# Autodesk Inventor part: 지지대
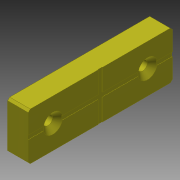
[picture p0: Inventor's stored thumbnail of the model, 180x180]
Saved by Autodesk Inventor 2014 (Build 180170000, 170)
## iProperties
Created: 2017-04
Part Number: 지지대
Material: 강철
Document SubType Name: Modeling
Designer: mduedu
Density: 7.85 g/cm^3
Mass: 97.8486 g
Surface Area: 48.4895 cm^2
Volume: 12.4648 cm^3
Appearance: 밝은 황색
Author: mduedu
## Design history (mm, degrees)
sketch "스케치1"
  geometry: L1 (23, -35)-(23, 35); L2 (0, -35)-(0, 35); L3 (0, 35)-(23, 35); L4 (0, -35)-(23, -35); 2 further points
  constraints: 8 end point, 2 parallel, 1 coincident, 1 midpoint, 1 perpendicular, 1 vertical
  dimensions: "d1" = 23 distance between parallel lines of L2 L1; "d15" = 70 distance of L1.start L1.end
extrude "돌출1" new body sketch "스케치1" distance "d2" = 8; taper "d3" = 0 deg
chamfer "모따기2" distance "d16" = 1; stored, may be unused: second distance "d17" = 2, angle "d18" = 45 deg
sketch "스케치2"
  geometry: L1 (1, -35)-(22, -35) reference; L2 (23, -34)-(23, 34) reference; L3 (22, 35)-(1, 35) reference; L4 (0, 34)-(0, -34) reference; L5 (11.5, 35)-(11.5, -35); L6 (23, 0)-(0, 0); L7 (1, -35)-(0, -34) reference; L8 (23, -34)-(22, -35) reference; L9 (22, 35)-(23, 34) reference; L10 (0, 34)-(1, 35) reference; 2 further points
  constraints: 4 end point, 4 midpoint, 1 point on line, 1 symmetric about line
  dimensions: "d7" = 12 distance from line of point (11.5, 23) L3
  node "투영된 루프1"
sketch "스케치3"
  geometry: 4 further points
  constraints: 2 coincident
hole "구멍1" sketch "스케치3" at (11.5, 23), (11.5, -23) diameter "d8" = 4.5; stored, may be unused: countersink angle "d12" = 90 deg, drill point angle "d14" = 0 deg; dims "d9" = 6, "d10" = 9.4, "d11" = 2, "d13" = 8
sketch "스케치4"
  geometry: L1 (-35, 22)-(-35, 1) reference; L2 (35, 1)-(35, 22) reference; L3 (34, 23)-(-34, 23) reference; L4 (-34, 0)-(34, 0) reference; L5 (-35, 11.5)-(35, 11.5); L6 (0, 23)-(0, 0); L7 (-35, 12.5)-(35, 12.5); L8 (-35, 10.5)-(35, 10.5); L9 (-1, 23)-(-1, 0); L10 (1, 23)-(1, 0)
  constraints: 12 end point, 8 point on line, 4 parallel, 3 midpoint, 3 perpendicular
  dimensions: "d19" = 1 distance between parallel lines of L7 L5; "d21" = 1 distance between parallel lines of L8 L5; "d22" = 1 distance between parallel lines of L9 L6; "d23" = 1 distance between parallel lines of L10 L6
extrude "돌출2" cut sketch "스케치4" distance "d24" = 0.2; taper "d25" = 0 deg
extrude "돌출3" cut sketch "스케치4" distance "d26" = 0.2; taper "d27" = 0 deg
fillet "모깎기1" dims "d28" = 0.2
node "솔리드2"
node "솔리드1"
